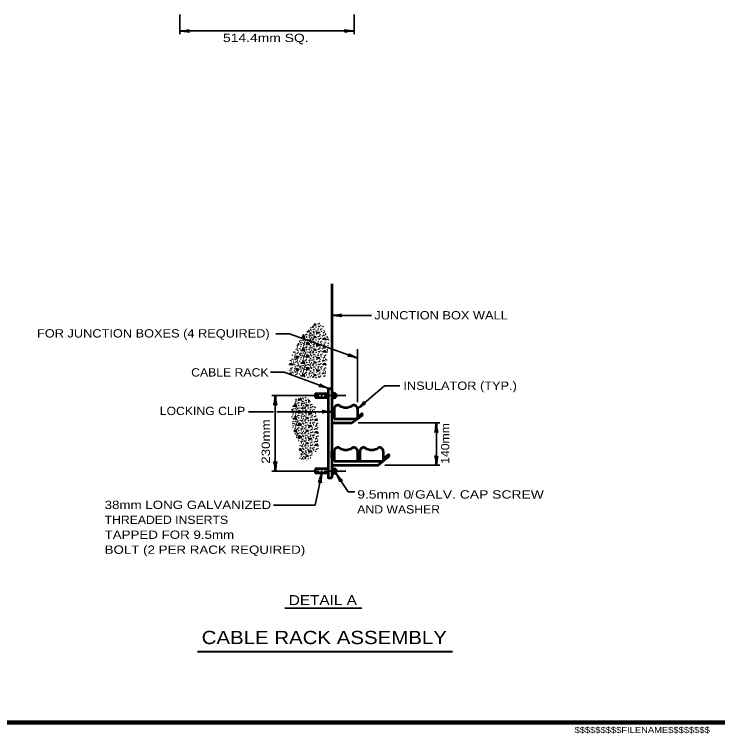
# Model space of a CAD drawing. Extents: x 918 to 1774, y -8 to 536.
# Drawn here: x 1291.6 to 1545.7, y -0.3 to 259.7 of the extents above; entities that cross this region are included whole.
import ezdxf

# ---------------------------------------------------------------- set-up
doc = ezdxf.new("R2010")
doc.units = 0
doc.header["$LTSCALE"] = 1.2
doc.layers.add('1', color=7, linetype='Continuous', lineweight=35)

msp = doc.modelspace()

# ---------------------------------------------------------------- linework, layer by layer
at = {"layer": '1'}
for p, q in [((1351.382, 259.655), (1351.382, 252.455)), ((1414.382, 259.655), (1414.382, 252.455)), ((1351.382, 253.655), (1414.382, 253.655)), ((1406.272, 150.847), (1420.672, 150.847)), ((1393.754, 139.766), (1393.754, 139.767)), ((1415.572, 119.497), (1415.572, 138.697)), ((1403.786, 129.038), (1403.258, 128.75)), ((1403.857, 128.876), (1403.738, 129.062)), ((1384.672, 121.897), (1401.772, 121.897)), ((1385.872, 121.897), (1385.872, 94.597)), ((1397.791, 120.145), (1398.182, 120.1)), ((1402.372, 121.897), (1402.972, 121.897)), ((1403.572, 121.897), (1411.372, 121.897)), ((1385.272, 116.023), (1376.189, 116.023)), ((1406.272, 116.023), (1386.472, 116.023)), ((1401.083, 113.192), (1400.887, 113.497)), ((1415.872, 111.997), (1445.272, 111.997)), ((1444.072, 111.997), (1444.072, 96.697)), ((1393.423, 109.369), (1392.511, 109)), ((1425.472, 96.697), (1445.272, 96.697)), ((1384.672, 94.597), (1401.772, 94.597)), ((1402.372, 94.597), (1402.972, 94.597)), ((1403.572, 94.597), (1411.372, 94.597)), ((1389.323, 44.98), (1417.108, 44.98))]:
    msp.add_line(p, q, dxfattribs=at)
at = {"layer": '1', "lineweight": 53}
for p, q in [((1406.272, 162.247), (1406.272, 124.447)), ((1400.272, 122.647), (1405.072, 122.647)), ((1400.272, 122.647), (1400.272, 121.147)), ((1406.272, 124.447), (1406.272, 113.977)), ((1406.272, 123.097), (1406.872, 123.097)), ((1406.872, 123.097), (1406.872, 120.697)), ((1406.872, 122.647), (1407.772, 122.647)), ((1407.772, 122.647), (1407.772, 121.147)), ((1400.272, 121.147), (1405.072, 121.147)), ((1406.272, 120.697), (1406.872, 120.697)), ((1406.872, 121.147), (1407.772, 121.147)), ((1407.172, 117.097), (1407.172, 113.497)), ((1415.572, 117.097), (1415.572, 113.497)), ((1406.272, 114.697), (1406.272, 99.397)), ((1413.472, 111.997), (1417.525, 114.892)), ((1406.272, 111.997), (1413.472, 111.997)), ((1407.172, 113.497), (1415.572, 113.497)), ((1407.172, 101.797), (1407.172, 98.197)), ((1415.572, 101.797), (1415.572, 98.197)), ((1416.472, 101.797), (1416.472, 98.197)), ((1424.872, 101.797), (1424.872, 98.197)), ((1406.272, 99.397), (1406.272, 92.047)), ((1415.572, 99.097), (1416.472, 99.097)), ((1405.072, 95.347), (1400.272, 95.347)), ((1400.272, 95.347), (1400.272, 93.847)), ((1405.072, 93.847), (1400.272, 93.847)), ((1406.872, 95.797), (1406.272, 95.797)), ((1406.872, 95.797), (1406.872, 93.397)), ((1406.872, 95.347), (1407.772, 95.347)), ((1406.872, 93.847), (1407.772, 93.847)), ((1407.772, 95.347), (1407.772, 93.847)), ((1406.872, 93.397), (1406.272, 93.397))]:
    msp.add_line(p, q, dxfattribs=at)
at = {"layer": '1', "lineweight": 40}
msp.add_line((1357.738, 29.375), (1449.849, 29.375), dxfattribs=at)
at = {"layer": '1', "lineweight": 158}
msp.add_line((1766.999, 3.718), (975.399, 3.718), dxfattribs=at)
at = {"layer": '1'}
for points in [[(1400.306, 147.902), (1399.85, 147.422), (1400.546, 147.374), (1400.306, 147.854)], [(1403.172, 146.943), (1402.994, 146.846), (1403.268, 146.796)], [(1415.572, 135.383), (1390.983, 144.195), (1386.014, 144.195)], [(1396.274, 143.174), (1395.146, 142.718), (1396.394, 142.574), (1396.274, 143.126)], [(1397.825, 145.483), (1398.17, 145.286), (1397.235, 144.83)], [(1400.306, 143.342), (1399.85, 142.862), (1400.546, 142.814), (1400.306, 143.294)], [(1394.05, 140.606), (1394.402, 140.534), (1393.795, 139.884)], [(1397.33, 141.206), (1398.17, 140.726), (1397.138, 140.222), (1397.282, 141.23)], [(1403.786, 142.718), (1402.994, 142.286), (1404.17, 142.07), (1403.738, 142.742)], [(1396.274, 138.614), (1395.146, 138.158), (1396.394, 138.014), (1396.274, 138.566)], [(1400.306, 138.782), (1399.85, 138.302), (1400.546, 138.254), (1400.306, 138.734)], [(1403.786, 138.158), (1402.994, 137.726), (1404.17, 137.51), (1403.738, 138.182)], [(1393.754, 135.206), (1393.466, 136.166), (1394.402, 135.974), (1393.73, 135.254)], [(1397.33, 136.646), (1398.17, 136.166), (1397.138, 135.662), (1397.282, 136.67)], [(1391.69, 133.598), (1390.898, 133.166), (1392.074, 132.95), (1391.642, 133.622)], [(1396.274, 134.054), (1395.146, 133.598), (1396.394, 133.454), (1396.274, 134.006)], [(1400.306, 134.222), (1399.85, 133.742), (1400.546, 133.694), (1400.306, 134.174)], [(1403.786, 133.598), (1402.994, 133.166), (1404.17, 132.95), (1403.738, 133.622)], [(1405.072, 124.447), (1389.132, 130.355), (1384.162, 130.355)], [(1393.754, 130.646), (1393.466, 131.606), (1394.402, 131.414), (1393.73, 130.694)], [(1397.33, 132.086), (1398.17, 131.606), (1397.138, 131.102), (1397.282, 132.11)], [(1396.274, 129.494), (1395.146, 129.038), (1396.394, 128.894), (1396.274, 129.446)], [(1400.306, 129.662), (1399.85, 129.182), (1400.546, 129.134), (1400.306, 129.614)], [(1415.572, 117.097), (1425.281, 125.384), (1430.835, 125.384)], [(1394.728, 120.938), (1395.319, 120.601), (1394.287, 120.097), (1394.395, 120.852)], [(1398.501, 119.811), (1398.223, 119.713), (1397.791, 120.145)], [(1393.423, 118.489), (1392.295, 118.033), (1393.543, 117.889), (1393.423, 118.441)], [(1397.455, 118.657), (1396.999, 118.177), (1397.695, 118.129), (1397.455, 118.609)], [(1400.352, 117.714), (1400.143, 117.601), (1400.377, 117.558)], [(1391.494, 115.86), (1391.551, 115.849), (1391.485, 115.778)], [(1394.479, 116.521), (1395.319, 116.041), (1394.287, 115.537), (1394.431, 116.545)], [(1393.423, 113.929), (1392.295, 113.473), (1393.543, 113.329), (1393.423, 113.881)], [(1394.479, 111.961), (1395.319, 111.481), (1394.287, 110.977), (1394.431, 111.985)], [(1397.455, 114.097), (1396.999, 113.617), (1397.695, 113.569), (1397.455, 114.049)], [(1400.935, 113.473), (1400.143, 113.041), (1401.137, 112.858)], [(1392.568, 108.881), (1393.543, 108.769), (1393.423, 109.321)], [(1397.455, 109.537), (1396.999, 109.057), (1397.695, 109.009), (1397.455, 109.489)], [(1394.479, 107.401), (1395.319, 106.921), (1394.287, 106.417), (1394.431, 107.425)], [(1400.935, 108.913), (1400.143, 108.481), (1401.319, 108.265), (1400.887, 108.937)], [(1397.455, 104.977), (1396.999, 104.497), (1397.695, 104.449), (1397.455, 104.929)], [(1400.935, 104.353), (1400.143, 103.921), (1401.319, 103.705), (1400.887, 104.377)], [(1394.538, 102.807), (1395.319, 102.361), (1394.522, 101.971)], [(1397.455, 100.417), (1396.999, 99.937), (1397.695, 99.889), (1397.455, 100.369)], [(1402.663, 93.847), (1400.264, 82.28), (1385.233, 82.28)], [(1407.772, 93.847), (1412.171, 87.139), (1414.578, 87.139)]]:
    msp.add_lwpolyline(points, dxfattribs=at)
for points in [[(1400.642, 144.83), (1401.89, 144.686), (1401.074, 144.398)], [(1400.642, 140.27), (1401.89, 140.126), (1401.074, 139.838)], [(1400.642, 135.71), (1401.89, 135.566), (1401.074, 135.278)], [(1400.642, 131.15), (1401.89, 131.006), (1401.074, 130.718)], [(1406.272, 114.697), (1406.272, 117.097), (1407.172, 117.097), (1407.172, 114.697)], [(1397.791, 115.585), (1399.039, 115.441), (1398.223, 115.153)], [(1397.791, 111.025), (1399.039, 110.881), (1398.223, 110.593)], [(1397.791, 106.465), (1399.039, 106.321), (1398.223, 106.033)], [(1397.791, 101.905), (1399.039, 101.761), (1398.223, 101.473)]]:
    msp.add_lwpolyline(points, close=True, dxfattribs=at)
at = {"layer": '1', "lineweight": 53}
for points in [[(1406.272, 92.047), (1405.072, 92.047), (1405.072, 124.447), (1406.272, 124.447)], [(1415.572, 114.234), (1417.176, 115.38), (1417.525, 114.892)], [(1406.272, 96.697), (1423.072, 96.697), (1427.176, 100.118)], [(1424.872, 98.978), (1426.792, 100.578), (1427.176, 100.118)], [(1407.172, 98.197), (1415.572, 98.197), (1424.872, 98.197)]]:
    msp.add_lwpolyline(points, dxfattribs=at)
msp.add_lwpolyline([(1406.272, 101.797), (1407.172, 101.797), (1407.172, 99.397), (1406.272, 99.397)], close=True, dxfattribs=at)
at = {"layer": '1'}
for centre in [(1398.67, 145.743), (1398.734, 146.412), (1399.433, 146.905), (1399.449, 146.523), (1399.64, 145.807), (1399.713, 146.809), (1400.142, 145.871), (1400.651, 146.602), (1401.383, 147.732), (1401.414, 145.998), (1401.51, 146.873), (1401.923, 147.939), (1401.923, 146.825), (1402.241, 145.743), (1402.305, 147.112), (1402.719, 145.998), (1395.791, 143.522), (1396.046, 143.898), (1396.555, 143.474), (1396.889, 143.866), (1397.191, 143.029), (1397.223, 144.009), (1398.113, 144.868), (1398.145, 143.586), (1398.161, 143.787), (1398.193, 143.045), (1398.511, 144.391), (1398.749, 143.649), (1398.781, 144.391), (1398.94, 145.393), (1399.338, 143.803), (1399.616, 144.834), (1399.776, 143.427), (1399.888, 144.853), (1399.888, 144.137), (1400.54, 145.25), (1400.858, 144.089), (1401.351, 145.521), (1401.383, 143.172), (1401.923, 143.379), (1402.051, 143.993), (1402.575, 145.123), (1402.894, 143.49), (1403.291, 144.63), (1403.371, 143.723), (1403.625, 145.393), (1403.673, 144.805), (1403.848, 143.57), (1404.086, 144.153), (1404.595, 143.093), (1394.678, 141.438), (1395.012, 140.993), (1395.171, 141.708), (1395.632, 140.961), (1395.95, 141.82), (1396.141, 140.563), (1396.427, 142.408), (1396.491, 140.483), (1396.507, 141.056), (1396.587, 141.422), (1396.714, 141.804), (1397.048, 142.011), (1397.684, 142.154), (1398.225, 141.979), (1398.606, 142.329), (1398.67, 141.183), (1398.734, 141.852), (1398.94, 140.833), (1399.004, 142.822), (1399.433, 142.345), (1399.449, 141.963), (1399.64, 141.247), (1399.713, 142.249), (1400.142, 141.311), (1400.54, 140.69), (1400.651, 142.042), (1401.351, 140.961), (1401.414, 141.438), (1401.51, 142.313), (1401.923, 142.265), (1402.241, 141.183), (1402.305, 142.552), (1402.575, 140.563), (1402.719, 141.438), (1403.625, 140.833), (1404.118, 141.04), (1404.595, 142.202), (1404.786, 142.838), (1405.056, 142.09), (1393.787, 138.723), (1393.899, 139.354), (1394.058, 138.167), (1394.121, 138.167), (1394.726, 138.851), (1395.123, 139.608), (1395.203, 140.261), (1395.791, 138.962), (1396.046, 139.338), (1396.157, 139.943), (1396.427, 137.848), (1396.555, 138.914), (1396.889, 139.306), (1397.191, 138.469), (1397.223, 139.449), (1398.113, 140.308), (1398.145, 139.026), (1398.161, 139.227), (1398.193, 138.485), (1398.511, 139.831), (1398.606, 137.769), (1398.749, 139.089), (1398.781, 139.831), (1399.004, 138.262), (1399.338, 139.243), (1399.433, 137.785), (1399.616, 140.274), (1399.776, 138.867), (1399.888, 140.293), (1399.888, 139.577), (1400.858, 139.529), (1401.383, 138.612), (1401.51, 137.753), (1401.923, 138.819), (1402.051, 139.433), (1402.305, 137.992), (1402.894, 138.93), (1403.291, 140.07), (1403.371, 139.163), (1403.673, 140.245), (1403.848, 139.01), (1404.086, 139.593), (1404.516, 139.354), (1404.595, 138.533), (1404.786, 138.278), (1392.022, 136.48), (1392.897, 135.478), (1392.945, 136.194), (1392.96, 137.53), (1393.104, 136.846), (1393.756, 137.133), (1394.201, 137.467), (1394.678, 136.878), (1395.012, 136.433), (1395.171, 137.148), (1395.203, 135.701), (1395.632, 136.401), (1395.95, 137.26), (1396.141, 136.003), (1396.157, 135.383), (1396.491, 135.923), (1396.507, 136.496), (1396.587, 136.862), (1396.714, 137.244), (1397.048, 137.451), (1397.684, 137.594), (1398.113, 135.748), (1398.225, 137.419), (1398.511, 135.271), (1398.67, 136.623), (1398.734, 137.292), (1398.781, 135.271), (1398.94, 136.273), (1399.449, 137.403), (1399.616, 135.714), (1399.64, 136.687), (1399.713, 137.689), (1399.888, 135.733), (1400.142, 136.751), (1400.54, 136.13), (1400.651, 137.482), (1401.351, 136.401), (1401.414, 136.878), (1401.923, 137.705), (1402.241, 136.623), (1402.575, 136.003), (1402.719, 136.878), (1403.291, 135.51), (1403.625, 136.273), (1403.673, 135.685), (1404.118, 136.48), (1404.595, 137.642), (1391.752, 134.45), (1391.99, 135.033), (1392.42, 134.794), (1392.499, 133.973), (1392.499, 133.082), (1392.69, 133.718), (1392.96, 132.97), (1393.119, 134.969), (1393.31, 133.973), (1393.756, 132.573), (1393.787, 134.163), (1393.899, 134.794), (1394.058, 133.607), (1394.121, 133.607), (1394.201, 132.907), (1394.726, 134.291), (1395.123, 135.048), (1395.171, 132.588), (1395.791, 134.402), (1395.95, 132.7), (1396.046, 134.778), (1396.427, 133.288), (1396.555, 134.354), (1396.714, 132.684), (1396.889, 134.746), (1397.048, 132.891), (1397.191, 133.909), (1397.223, 134.889), (1397.684, 133.034), (1398.145, 134.466), (1398.161, 134.667), (1398.193, 133.925), (1398.225, 132.859), (1398.606, 133.209), (1398.734, 132.732), (1398.749, 134.529), (1399.004, 133.702), (1399.338, 134.683), (1399.433, 133.225), (1399.449, 132.843), (1399.713, 133.129), (1399.776, 134.307), (1399.888, 135.017), (1400.651, 132.922), (1400.858, 134.969), (1401.383, 134.052), (1401.51, 133.193), (1401.923, 134.259), (1401.923, 133.145), (1402.051, 134.873), (1402.305, 133.432), (1402.894, 134.37), (1403.371, 134.603), (1403.848, 134.45), (1404.086, 135.033), (1404.516, 134.794), (1391.195, 130.95), (1391.275, 130.043), (1391.529, 131.713), (1391.577, 131.125), (1391.99, 130.473), (1392.022, 131.92), (1392.42, 130.234), (1392.897, 130.918), (1392.945, 131.634), (1393.104, 132.286), (1393.119, 130.409), (1393.899, 130.234), (1394.678, 132.318), (1395.012, 131.873), (1395.123, 130.488), (1395.203, 131.141), (1395.632, 131.841), (1396.046, 130.218), (1396.141, 131.443), (1396.157, 130.823), (1396.491, 131.363), (1396.507, 131.936), (1396.587, 132.302), (1396.889, 130.186), (1397.223, 130.329), (1398.113, 131.188), (1398.161, 130.107), (1398.511, 130.711), (1398.67, 132.063), (1398.749, 129.969), (1398.781, 130.711), (1398.94, 131.713), (1399.338, 130.123), (1399.616, 131.154), (1399.64, 132.127), (1399.888, 131.173), (1399.888, 130.457), (1400.142, 132.191), (1400.54, 131.57), (1400.858, 130.409), (1401.351, 131.841), (1401.414, 132.318), (1402.051, 130.313), (1402.241, 132.063), (1402.575, 131.443), (1402.719, 132.318), (1403.291, 130.95), (1403.371, 130.043), (1403.625, 131.713), (1403.673, 131.125), (1404.086, 130.473), (1404.118, 131.92), (1391.752, 129.89), (1393.787, 129.603), (1394.726, 129.731), (1395.791, 129.842), (1396.427, 128.728), (1396.555, 129.794), (1397.191, 129.349), (1397.684, 128.474), (1398.145, 129.906), (1398.193, 129.365), (1398.606, 128.649), (1399.004, 129.142), (1399.433, 128.665), (1399.713, 128.569), (1399.776, 129.747), (1400.651, 128.362), (1401.383, 129.492), (1401.51, 128.633), (1401.923, 129.699), (1401.923, 128.585), (1402.305, 128.872), (1402.894, 129.81), (1403.848, 129.89), (1393.291, 120.438), (1393.307, 119.817), (1393.641, 120.358), (1395.263, 120.183), (1395.66, 119.706), (1395.819, 121.058), (1395.931, 119.706), (1396.09, 120.708), (1396.766, 120.149), (1396.79, 121.122), (1397.037, 120.167), (1392.321, 117.023), (1392.941, 118.837), (1393.1, 117.134), (1393.195, 119.213), (1393.577, 117.723), (1393.704, 118.789), (1393.863, 117.118), (1394.038, 119.181), (1394.197, 117.325), (1394.34, 118.343), (1394.372, 119.324), (1394.833, 117.468), (1395.295, 118.9), (1395.311, 119.101), (1395.342, 118.359), (1395.374, 117.293), (1395.756, 117.643), (1395.883, 117.166), (1395.899, 118.964), (1396.153, 118.137), (1396.487, 119.117), (1396.583, 117.659), (1396.599, 117.278), (1396.862, 117.564), (1396.926, 118.741), (1397.037, 119.451), (1397.801, 117.357), (1398.008, 119.404), (1398.532, 118.487), (1398.659, 117.628), (1399.073, 118.693), (1399.073, 117.58), (1399.455, 117.866), (1391.828, 116.753), (1392.162, 116.307), (1392.273, 114.923), (1392.352, 115.575), (1392.782, 116.275), (1393.195, 114.653), (1393.291, 115.878), (1393.307, 115.257), (1393.641, 115.798), (1393.657, 116.371), (1393.736, 116.737), (1394.038, 114.621), (1394.372, 114.764), (1395.263, 115.623), (1395.311, 114.541), (1395.66, 115.146), (1395.819, 116.498), (1395.899, 114.404), (1395.931, 115.146), (1396.09, 116.148), (1396.487, 114.557), (1396.766, 115.589), (1396.79, 116.562), (1397.037, 115.607), (1397.037, 114.891), (1397.292, 116.625), (1397.689, 116.005), (1398.008, 114.844), (1398.501, 116.275), (1398.564, 116.753), (1399.2, 114.748), (1399.391, 116.498), (1399.725, 115.878), (1399.868, 116.753), (1400.441, 115.384), (1400.52, 114.478), (1391.875, 114.165), (1392.321, 112.463), (1392.941, 114.277), (1393.1, 112.574), (1393.577, 113.163), (1393.657, 111.811), (1393.704, 114.229), (1393.736, 112.177), (1393.863, 112.558), (1394.197, 112.765), (1394.34, 113.783), (1394.833, 112.908), (1395.295, 114.34), (1395.342, 113.799), (1395.374, 112.733), (1395.756, 113.083), (1395.819, 111.938), (1395.883, 112.606), (1396.153, 113.577), (1396.583, 113.099), (1396.599, 112.718), (1396.79, 112.002), (1396.862, 113.004), (1396.926, 114.181), (1397.292, 112.065), (1397.801, 112.797), (1398.532, 113.927), (1398.564, 112.193), (1398.659, 113.068), (1399.073, 114.133), (1399.073, 113.02), (1399.391, 111.938), (1399.455, 113.306), (1399.868, 112.193), (1400.043, 114.245), (1401.268, 111.795), (1392.162, 111.747), (1392.273, 110.363), (1392.352, 111.015), (1392.782, 111.715), (1392.941, 109.717), (1393.195, 110.093), (1393.291, 111.318), (1393.307, 110.697), (1393.641, 111.238), (1393.704, 109.669), (1394.038, 110.061), (1394.34, 109.223), (1394.372, 110.204), (1395.263, 111.063), (1395.295, 109.78), (1395.311, 109.981), (1395.342, 109.239), (1395.66, 110.586), (1395.899, 109.844), (1395.931, 110.586), (1396.09, 111.588), (1396.487, 109.997), (1396.766, 111.029), (1396.926, 109.621), (1397.037, 111.047), (1397.037, 110.331), (1397.689, 111.445), (1398.008, 110.284), (1398.501, 111.715), (1398.532, 109.367), (1399.073, 109.573), (1399.2, 110.188), (1399.725, 111.318), (1400.043, 109.685), (1400.441, 110.824), (1400.52, 109.918), (1400.775, 111.588), (1400.822, 110.999), (1400.997, 109.764), (1401.236, 110.347), (1393.1, 108.014), (1393.577, 108.603), (1393.657, 107.251), (1393.736, 107.617), (1393.863, 107.998), (1394.197, 108.205), (1394.833, 108.348), (1395.374, 108.173), (1395.756, 108.523), (1395.819, 107.378), (1395.883, 108.046), (1396.09, 107.028), (1396.153, 109.017), (1396.583, 108.539), (1396.599, 108.158), (1396.79, 107.442), (1396.862, 108.444), (1397.292, 107.505), (1397.689, 106.885), (1397.801, 108.237), (1398.501, 107.155), (1398.564, 107.633), (1398.659, 108.508), (1399.073, 108.46), (1399.391, 107.378), (1399.455, 108.746), (1399.725, 106.758), (1399.868, 107.633), (1400.775, 107.028), (1401.268, 107.235), (1394.372, 105.644), (1395.263, 106.503), (1395.295, 105.22), (1395.311, 105.421), (1395.342, 104.679), (1395.66, 106.026), (1395.756, 103.963), (1395.899, 105.284), (1395.931, 106.026), (1396.153, 104.457), (1396.487, 105.437), (1396.583, 103.979), (1396.766, 106.469), (1396.926, 105.061), (1397.037, 106.487), (1397.037, 105.771), (1398.008, 105.724), (1398.532, 104.807), (1399.073, 105.013), (1399.2, 105.628), (1399.455, 104.186), (1400.043, 105.125), (1400.441, 106.264), (1400.52, 105.358), (1400.822, 106.439), (1400.997, 105.204), (1401.236, 105.787), (1394.833, 103.788), (1395.263, 101.943), (1395.374, 103.613), (1395.66, 101.466), (1395.819, 102.818), (1395.883, 103.486), (1395.931, 101.466), (1396.09, 102.468), (1396.599, 103.598), (1396.766, 101.909), (1396.79, 102.882), (1396.862, 103.884), (1397.037, 101.927), (1397.292, 102.945), (1397.689, 102.325), (1397.801, 103.677), (1398.501, 102.595), (1398.564, 103.073), (1398.659, 103.948), (1399.073, 103.9), (1399.391, 102.818), (1399.725, 102.198), (1399.868, 103.073), (1400.441, 101.704), (1400.775, 102.468), (1401.268, 102.675), (1394.833, 99.228), (1395.295, 100.66), (1395.311, 100.861), (1395.342, 100.119), (1395.374, 99.053), (1395.756, 99.403), (1395.883, 98.926), (1395.899, 100.724), (1396.153, 99.897), (1396.487, 100.877), (1396.583, 99.419), (1396.599, 99.038), (1396.862, 99.324), (1396.926, 100.501), (1397.037, 101.211), (1397.801, 99.117), (1398.008, 101.164), (1398.532, 100.247), (1398.659, 99.388), (1399.073, 100.453), (1399.2, 101.068)]:
    msp.add_circle(centre, 0.0318, dxfattribs=at)
for centre, start, end in [((1405.041, 140.754), 90.7068, 262.46216), ((1393.31, 138.533), 183.01325, 94.63547), ((1404.993, 140.038), 81.7766, 271.39236), ((1392.499, 137.642), 230.82288, 46.82584), ((1391.275, 134.603), 206.21163, 115.66112), ((1393.31, 129.413), 291.77182, 216.03601), ((1397.689, 120.565), 163.57975, 292.03289), ((1393.641, 106.678), 257.94855, 153.06656), ((1397.292, 98.385), 20.334, 145.41282)]:
    msp.add_arc(centre, 0.0318, start, end, dxfattribs=at)
at = {"layer": '1', "lineweight": 53}
for centre, radius, start, end in [((1408.451, 117.128), 1.28, 65.99256, 181.38757), ((1411.372, 121.913), 4.34, 236.42696, 303.57304), ((1414.292, 117.128), 1.28, 358.61243, 114.00744), ((1408.451, 101.828), 1.28, 65.99256, 181.38757), ((1411.372, 106.613), 4.34, 236.42696, 303.57304), ((1414.292, 101.828), 1.28, 358.61243, 114.00744), ((1417.751, 101.828), 1.28, 65.99256, 181.38757), ((1420.672, 106.613), 4.34, 236.42696, 303.57304), ((1423.592, 101.828), 1.28, 358.61243, 114.00744)]:
    msp.add_arc(centre, radius, start, end, dxfattribs=at)
at = {"layer": '1', "lineweight": 40}
for centre, major_axis, ratio, start_param, end_param in [((1352.702, 253.977), (-2.143, -0.187), 0.122415, 0.8963533, 3.1415927), ((1352.738, 253.392), (-2.108, 0.211), 0.07063, 3.1407148, 5.41811), ((1413.062, 253.32), (2.143, 0.187), 0.122415, 0.8963533, 3.1415927), ((1413.026, 253.905), (2.108, -0.211), 0.07063, 3.1407148, 5.41811), ((1407.616, 150.593), (-2.108, 0.211), 0.07063, 3.1407148, 5.41811), ((1407.616, 150.593), (-2.108, 0.211), 0.07063, 3.1407148, 5.41811), ((1407.581, 151.179), (-2.143, -0.187), 0.122415, 0.8963533, 3.1415927), ((1407.581, 151.179), (-2.143, -0.187), 0.122415, 0.8963533, 3.1415927), ((1414.227, 135.513), (2.08, -0.547), 0.122415, 0.8963533, 3.1415927), ((1414.227, 135.513), (2.08, -0.547), 0.122415, 0.8963533, 3.1415927), ((1414.392, 136.076), (-1.913, 0.91), 0.07063, 6.2823074, 8.5597026), ((1414.392, 136.076), (-1.913, 0.91), 0.07063, 6.2823074, 8.5597026), ((1403.729, 124.591), (2.074, -0.569), 0.122415, 0.8963533, 3.1415927), ((1403.729, 124.591), (2.074, -0.569), 0.122415, 0.8963533, 3.1415927), ((1403.899, 125.152), (-1.903, 0.93), 0.07063, 6.2823074, 8.5597026), ((1403.899, 125.152), (-1.903, 0.93), 0.07063, 6.2823074, 8.5597026), ((1385.618, 120.552), (0.211, 2.108), 0.07063, 3.1407148, 5.41811), ((1385.618, 120.552), (0.211, 2.108), 0.07063, 3.1407148, 5.41811), ((1386.203, 120.588), (-0.187, 2.143), 0.122415, 0.8963533, 3.1415927), ((1386.203, 120.588), (-0.187, 2.143), 0.122415, 0.8963533, 3.1415927), ((1416.353, 118.199), (-1.508, -1.534), 0.122415, 0.8963533, 3.1415927), ((1416.759, 117.777), (-1.74, -1.208), 0.07063, 3.1407148, 5.41811), ((1404.962, 115.692), (2.143, 0.187), 0.122415, 0.8963533, 3.1415927), ((1404.962, 115.692), (2.143, 0.187), 0.122415, 0.8963533, 3.1415927), ((1404.927, 116.277), (2.108, -0.211), 0.07063, 3.1407148, 5.41811), ((1404.927, 116.277), (2.108, -0.211), 0.07063, 3.1407148, 5.41811), ((1443.818, 110.652), (0.211, 2.108), 0.07063, 3.1407148, 5.41811), ((1443.818, 110.652), (0.211, 2.108), 0.07063, 3.1407148, 5.41811), ((1444.403, 110.688), (-0.187, 2.143), 0.122415, 0.8963533, 3.1415927), ((1444.403, 110.688), (-0.187, 2.143), 0.122415, 0.8963533, 3.1415927), ((1443.74, 98.006), (0.187, -2.143), 0.122415, 0.8963533, 3.1415927), ((1443.74, 98.006), (0.187, -2.143), 0.122415, 0.8963533, 3.1415927), ((1444.326, 98.042), (-0.211, -2.108), 0.07063, 3.1407148, 5.41811), ((1444.326, 98.042), (-0.211, -2.108), 0.07063, 3.1407148, 5.41811), ((1385.54, 95.906), (0.187, -2.143), 0.122415, 0.8963533, 3.1415927), ((1386.126, 95.942), (-0.211, -2.108), 0.07063, 3.1407148, 5.41811), ((1402.141, 92.582), (-0.634, -2.021), 0.07063, 6.2823074, 8.5597026), ((1402.141, 92.582), (-0.634, -2.021), 0.07063, 6.2823074, 8.5597026), ((1402.721, 92.498), (0.252, 2.136), 0.122415, 0.8963533, 3.1415927), ((1402.721, 92.498), (0.252, 2.136), 0.122415, 0.8963533, 3.1415927), ((1408.297, 92.583), (-0.98, 1.878), 0.07063, 3.1407148, 5.41811), ((1408.767, 92.934), (-1.332, 1.689), 0.122415, 0.8963533, 3.1415927)]:
    msp.add_ellipse(centre, major_axis=major_axis, ratio=ratio, start_param=start_param, end_param=end_param, dxfattribs=at)

# ---------------------------------------------------------------- texts
at = {"layer": '1'}
for s, height, width, p in [('514.4mm SQ.', 3, 1.25, (1366.97, 249.66)), ('JUNCTION BOX WALL', 3, 1.15, (1421.671, 149.402)), ('FOR JUNCTION BOXES (4 REQUIRED)', 3, 1.15, (1299.764, 142.866)), ('CABLE RACK', 3, 1.1, (1355.473, 128.762)), ('INSULATOR (TYP.)', 3, 1.15, (1432.159, 123.946)), ('LOCKING CLIP', 3, 1.1, (1344.125, 114.83)), ('9.5mm 0 GALV. CAP SCREW', 3, 1.25, (1415.481, 84.655)), ('38mm LONG GALVANIZED', 3, 1.2, (1324.194, 80.885)), ('AND WASHER', 3, 1.1, (1415.481, 79.255)), ('THREADED INSERTS', 3, 1.1, (1324.194, 75.484)), ('TAPPED FOR 9.5mm', 3, 1.2, (1324.194, 70.085)), ('BOLT (2 PER RACK REQUIRED)', 3, 1.2, (1324.194, 64.684)), ('DETAIL A', 3.6, 1.15, (1390.737, 46.159)), ('CABLE RACK ASSEMBLY', 4.8, 1.15, (1359.273, 32.038)), ('$$$$$$$$$FILENAME$$$$$$$$', 2.2, 1.15, (1493.999, -0.082))]:
    msp.add_text(s, height=height, dxfattribs=dict(at, width=width)).set_placement(p)
for s, width, p in [('230mm', 1.2, (1383.913, 97.241)), ('140mm', 1.1, (1448.747, 97.203))]:
    msp.add_text(s, height=3, rotation=90, dxfattribs=dict(at, width=width)).set_placement(p)
msp.add_text('/', height=3, dxfattribs=at).set_placement((1434.804, 84.546))

doc.saveas('drawing.dxf')
